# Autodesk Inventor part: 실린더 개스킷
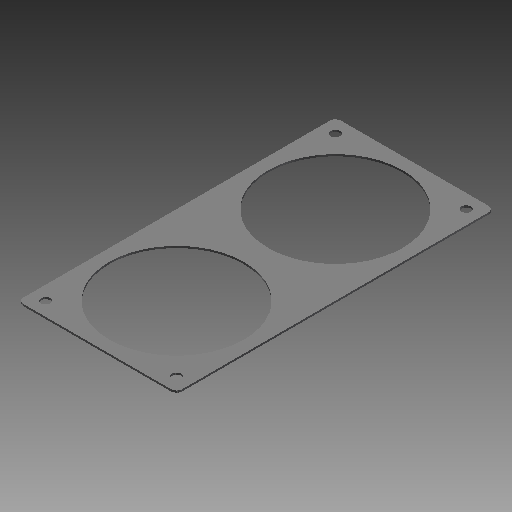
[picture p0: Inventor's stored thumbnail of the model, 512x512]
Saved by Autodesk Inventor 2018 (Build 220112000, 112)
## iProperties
Created: 2019-08
Part Number: 실린더 개스킷
Material: 고무
Document SubType Name: Modeling
Designer: mduedu
Density: 0.93 g/cm^3
Appearance: 고무 - 검은색 - 버전 1.1
Mass: 5.78528 g
Surface Area: 134.615 cm^2
Volume: 6.22073 cm^3
Author: mduedu
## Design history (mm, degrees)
sketch "스케치1"
  geometry: L1 (42.5, -42.5)-(-42.5, -42.5); L2 (-42.5, -42.5)-(-42.5, 127.5); L3 (-42.5, 127.5)-(42.5, 127.5); L4 (42.5, 127.5)-(42.5, -42.5); 2 further points
  constraints: 8 end point, 2 parallel, 1 horizontal, 1 midpoint, 1 perpendicular, 1 vertical alignment
  dimensions: "d1" = 85 distance of L1.start L1.end; "d3" = 170 distance of L3.end L1.start; "d4" = 42.5 distance from line of L1 point (0, 0)
extrude "돌출1" new body sketch "스케치1" distance "d5" = 1; taper "d6" = 0 deg
sketch "스케치2"
  geometry: C1 r 36 at (0, 0); C2 r 36 at (0, 85); 1 further point
  constraints: 2 centre point, 1 coincident, 1 vertical alignment
  dimensions: "d7" = 72 diameter of C1; "d8" = 72 diameter of C2; "d9" = 85 distance of C2.centre point (0, 0)
extrude "돌출2" cut sketch "스케치2" extent not by distance; stored distance "d10" = 1; taper "d11" = 0 deg
sketch "스케치3"
  geometry: L1 (-35, -35)-(35, -35); L2 (35, -35)-(35, 35); L3 (35, 35)-(-35, 35); L4 (-35, 35)-(-35, -35); L5 (-35, -35)-(35, 35); L6 (35, -35)-(-35, 35); L7 (-35, 50)-(35, 50); L8 (35, 50)-(35, 120); L9 (35, 120)-(-35, 120); L10 (-35, 120)-(-35, 50); L11 (-35, 50)-(35, 120); L12 (35, 50)-(-35, 120); C1 r 36 at (0, 85) reference; 5 further points
  constraints: 24 end point, 4 coincident, 4 midpoint, 4 parallel, 2 horizontal, 2 perpendicular
  dimensions: "d12" = 70 distance of L3.end L2.end; "d13" = 70 distance of L2.end L1.end; "d14" = 70 distance of L9.end L8.end; "d15" = 70 distance of L8.end L7.end
hole "구멍1" sketch "스케치3" at (35, -35), (-35, -35), (-35, 120), (35, 120) diameter "d16" = 5; stored, may be unused: countersink angle "d20" = 90 deg, drill point angle "d22" = 118 deg; dims "d17" = 6, "d18" = 4, "d19" = 2, "d21" = 8
fillet "모깎기1" dims "d23" = 3
node "솔리드2"
node "솔리드1"
